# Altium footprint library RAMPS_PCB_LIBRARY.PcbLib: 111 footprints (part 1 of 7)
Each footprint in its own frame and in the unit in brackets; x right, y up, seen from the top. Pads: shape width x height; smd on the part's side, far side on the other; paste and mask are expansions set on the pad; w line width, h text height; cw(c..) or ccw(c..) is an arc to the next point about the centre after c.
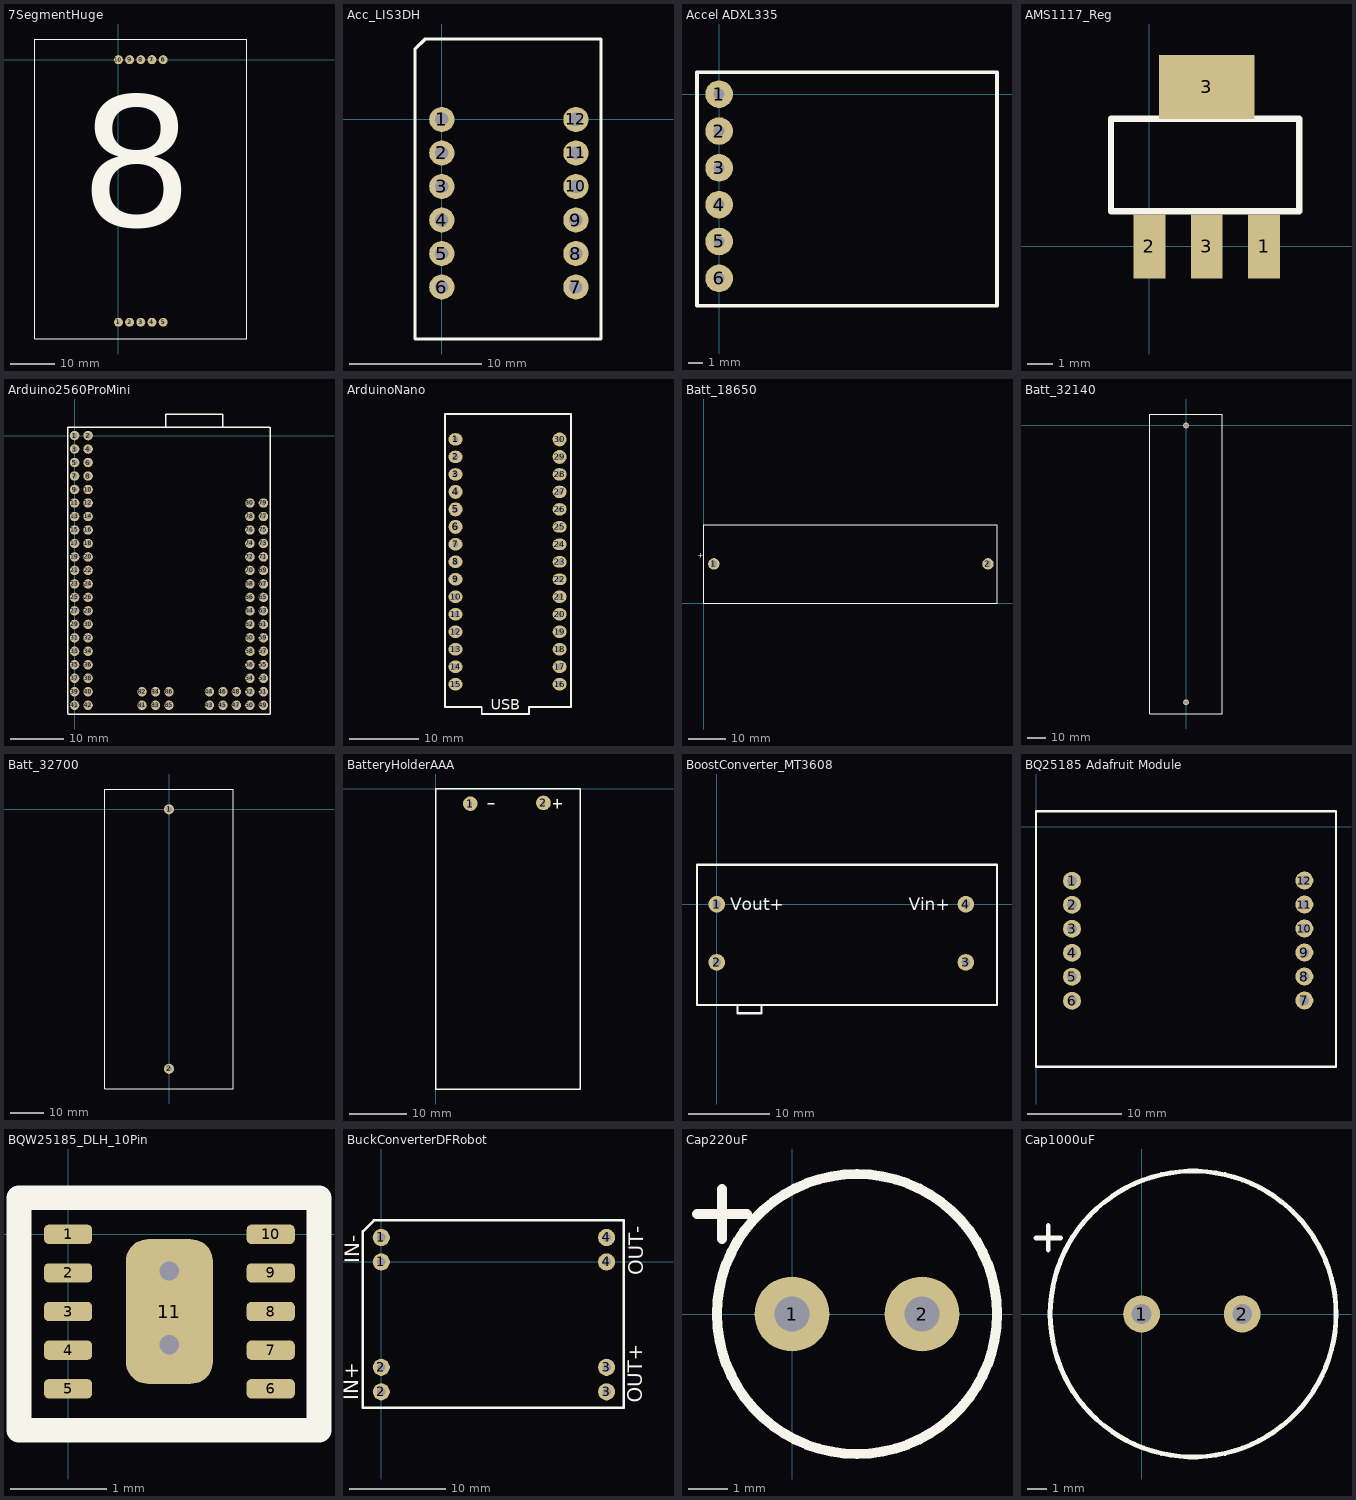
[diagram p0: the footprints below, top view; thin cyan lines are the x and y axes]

## 7SegmentHuge [mil]
pads (10):
  round 80 hole 30: 1(0,-2350) 2(100,-2350) 3(200,-2350) 4(300,-2350) 5(400,-2350) 6(400,0) 7(300,0) 8(200,0) 9(100,0) 10(0,0)
Top Overlay:
  lines w10: -750,-2500 1150,-2500 1150,185 -750,185 -750,-2500
  text "." at 750,-2075 h2000
  text "8" at -345,-1870.56 h2000

## Acc_LIS3DH [mil]
pads (12):
  round 75 hole 40: 1(0,0) 2(0,-100) 3(0,-200) 4(0,-300) 5(0,-400) 6(0,-500) 7(400,-500) 8(400,-400) 9(400,-300) 10(400,-200) 11(400,-100) 12(400,0)
Top Overlay:
  lines w10: -80,-655 475,-655 475,240 -50,240 -80,210 -80,-655

## Accel ADXL335 [mil]
pads (6):
  round 75 hole 30: 1(0,0) 2(0,-100) 3(0,-200) 4(0,-300) 5(0,-400) 6(0,-500)
Top Overlay:
  lines w10: -60,-575 -60,60 755,60 755,-575 -60,-575

## AMS1117_Reg [mil]
pads (4):
  rect 50x100 smd: 1(180,0) 2(0,0) 3(90,0)
  rect 150x100 smd: 3(90,250)
Top Overlay:
  region: -25,-60
  region: -25,-60
  region: -120,-145
  region: -120,-145
  lines w10: -60,55 -60,200 235,200 235,55 -60,55

## Arduino2560ProMini [mil]
pads (86):
  round 70 hole 40: 1(0,0) 2(100,0) 3(0,-100) 4(100,-100) 5(0,-200) 6(100,-200) 7(0,-300) 8(100,-300) 9(0,-400) 10(100,-400) 11(0,-500) 12(100,-500) 13(0,-600) 14(100,-600) 15(0,-700) 16(100,-700) 17(0,-800) 18(100,-800) 19(0,-900) 20(100,-900) 21(0,-1000) 22(100,-1000) 23(0,-1100) 24(100,-1100) 25(0,-1200) 26(100,-1200) 27(0,-1300) 28(100,-1300) 29(0,-1400) 30(100,-1400) 31(0,-1500) 32(100,-1500) 33(0,-1600) 34(100,-1600) 35(0,-1700) 36(100,-1700) 37(0,-1800) 38(100,-1800) 39(0,-1900) 40(100,-1900) 41(0,-2000) 42(100,-2000) 43(1000,-2000) 44(1000,-1900) 45(1100,-2000) 46(1100,-1900) 47(1200,-2000) 48(1200,-1900) 49(1400,-2000) 50(1300,-2000) 51(1400,-1900) 52(1300,-1900) 53(1400,-1800) 54(1300,-1800) 55(1400,-1700) 56(1300,-1700) 57(1400,-1600) 58(1300,-1600) 59(1400,-1500) 60(1300,-1500) 61(1400,-1400) 62(1300,-1400) 63(1400,-1300) 64(1300,-1300) 65(1400,-1200) 66(1300,-1200) 67(1400,-1100) 68(1300,-1100) 69(1400,-1000) 70(1300,-1000) 71(1400,-900) 72(1300,-900) 73(1400,-800) 74(1300,-800) 75(1400,-700) 76(1300,-700) 77(1400,-600) 78(1300,-600) 79(1400,-500) 80(1300,-500) 81(500,-2000) 82(500,-1900) 83(600,-2000) 84(600,-1900) 85(700,-2000) 86(700,-1900)
Top Overlay:
  lines w10: -50,-2065 1446.06,-2065 ; -50,-2060 -50,60 1446.06,60 ; 675,60 675,160 1100,160 1100,65 ; 1450,-2065 1450,60.98

## ArduinoNano [mil]
pads (30):
  oval 80x70 hole 35: 1(47965,46725) 2(47965,46625) 3(47965,46525) 7(47965,46125) 8(47965,46025) 9(47965,45925) 10(47965,45825) 11(47965,45725) 12(47965,45625) 13(47965,45525) 14(47965,45425) 15(47965,45325) 16(48560,45325) 17(48560,45425) 18(48560,45525) 19(48560,45625) 20(48560,45725) 21(48560,45825) 26(48560,46325) 27(48560,46425) 28(48560,46525)
  round 80 hole 35: 4(47965,46425) 5(47965,46325) 6(47965,46225) 29(48560,46625) 30(48560,46725)
  oval 80x65 hole 35: 22(48560,45925) 23(48560,46025) 24(48560,46125) 25(48560,46225)
Top Overlay:
  lines w10: 47905,45195 47905,46725 47905,46870 48625,46870 48625,45195 48615,45195 48385,45195 48385,45155 48115,45155 48115,45195 47905,45195
  text "USB" at 48165,45180 h60

## Batt_18650 [mil]
pads (2):
  round 120 hole 50 slot 70 at 90 deg: 1(106.3,413.39) 2(2976.38,413.39)
Top Overlay:
  lines w10: 0,0 3070.87,0 3070.87,824.13 3070,825 0,825 0,0
  text "+" at -70,480 h60

## Batt_32140 [mil]
pads (2):
  round 120 hole 50 slot 70 at 0 deg: 1(0,0) 2(0,-5787.4)
Top Overlay:
  lines w10: -760,-6030 760,-6030 760,240 -760,240 -760,-6030

## Batt_32700 [mil]
pads (2):
  round 120 hole 50 slot 70 at 0 deg: 1(0,0) 2(0,-3070.87)
Top Overlay:
  lines w10: -760,-3310 760,-3310 760,240 -760,240 -760,-3310

## BatteryHolderAAA [mil]
pads (2):
  round 100 hole 30: 1(235,-100) 2(735,-95)
Top Overlay:
  lines w10: 355,-100 400,-100 ; 800,-100 860,-100 ; 830,-130 830,-70 ; 0,-2050 0,0 985,0 985,-2050 0,-2050

## BoostConverter_MT3608 [mil]
pads (4):
  round 80 hole 40: 1(0,0) 2(0,-280) 3(1200,-280) 4(1200,0)
Top Overlay:
  lines w10: -95,-485 -95,190 ; -90,-485 1350,-485 1350,190 -90,190 ; 100,-485 100,-525 215,-525 215,-490
  text "Vout+" at 65,-30 h60
  text "Vin+" at 925,-30 h60

## BQ25185 Adafruit Module [mil]
pads (12):
  round 75 hole 40: 1(150,-225) 2(150,-325) 3(150,-425) 4(150,-525) 5(150,-625) 6(150,-725) 7(1118.23,-723.91) 8(1118.23,-623.91) 9(1118.23,-523.91) 10(1118.23,-423.91) 11(1118.23,-323.91) 12(1118.23,-223.91)
Top Overlay:
  lines w10: 0,-1000 0,65 1250,65 1250,-1000 0,-1000

## BQW25185_DLH_10Pin [mm]
pads (11):
  rrect50% 0.5x0.2 smd: 1(0,0) 2(0,-0.4) 3(0,-0.8) 4(0,-1.2) 5(0,-1.6) 6(2.1,-1.6) 7(2.1,-1.2) 8(2.1,-0.8) 9(2.1,-0.4) 10(2.1,0)
  rrect50% 0.9x1.5 smd: 11(1.05,-0.8)
via 1.05,-0.381 diameter 0.5 hole 0.2
via 1.05,-1.143 diameter 0.5 hole 0.2
Top Overlay:
  lines w0.254: -0.508,-2.032 2.6,-2.032 2.6,0.381 -0.508,0.381 -0.508,-2.032

## BuckConverterDFRobot [mil]
pads (8):
  round 70 hole 35: 1(0,0) 1(0,100) 2(0,-530) 2(0,-430) 3(920,-530) 3(920,-430) 4(920,0) 4(920,100)
Top Overlay:
  lines w10: -75,-595 990,-595 990,170 -30,170 -75,125 -75,-595
  text "OUT-" at 1070,-55 h60
  text "OUT+" at 1065,-575 h60
  text "IN+" at -95,-565 h60
  text "IN-" at -90,-5 h60

## Cap220uF [mil]
pads (2):
  round 75 hole 35: 1(0,0) 2(130,0)
Top Overlay:
  circle w10: c65,0 r140
  lines w10: -95,100 -45,100 ; -70,75 -70,125

## Cap1000uF [mil]
pads (2):
  round 75 hole 40: 1(0,0) 2(205,0)
Top Overlay:
  circle w10: c105,0 r291.08
  lines w10: -215,155 -165,155 ; -190,130 -190,180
